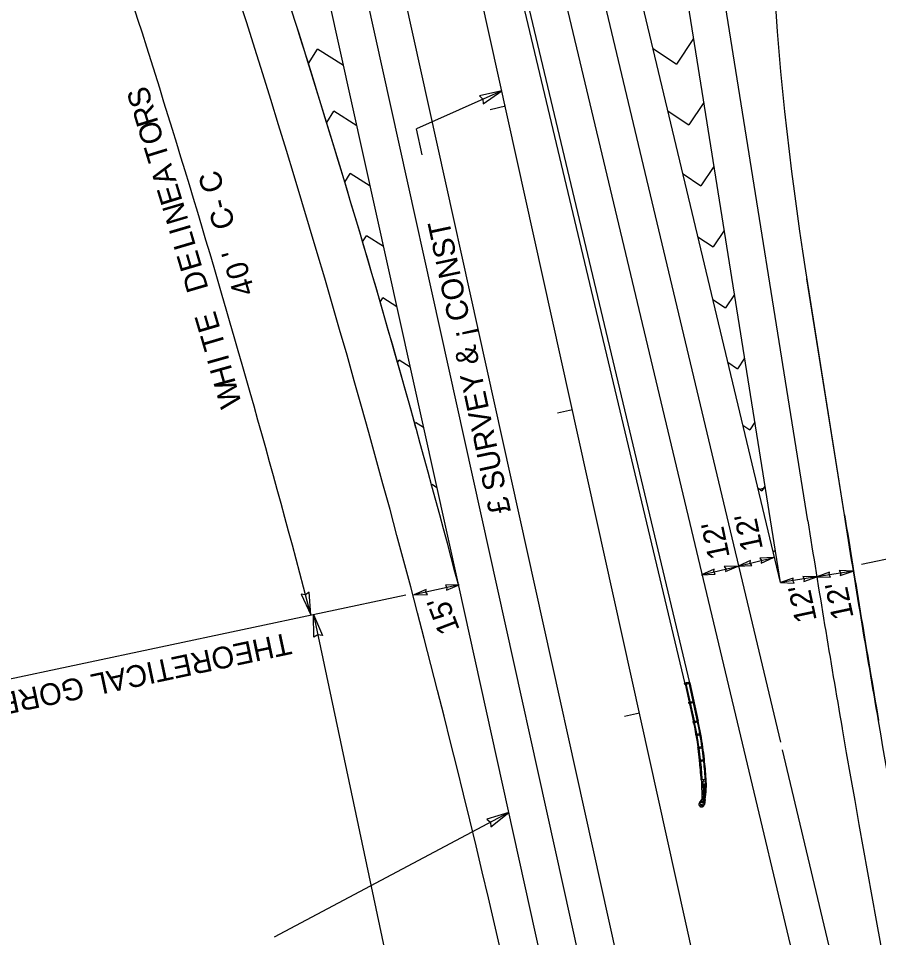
# Model space of a CAD drawing. Extents: x 578088 to 579220, y 1508751 to 1510398.
# Drawn here: x 578418.2 to 578695, y 1509092.1 to 1509387.9 of the extents above; entities that cross this region are included whole.
import ezdxf

# ---------------------------------------------------------------- set-up
doc = ezdxf.new("R2010")
doc.units = 0
for name, color, linetype in [('1', 7, 'Continuous'), ('18', 7, 'Continuous'), ('2', 7, 'Continuous'), ('28', 7, 'Continuous'), ('41', 7, 'Continuous'), ('46', 7, 'Continuous'), ('52', 7, 'Continuous'), ('8', 7, 'Continuous')]:
    doc.layers.add(name, color=color, linetype=linetype)

msp = doc.modelspace()

# ---------------------------------------------------------------- linework, layer by layer
at = {"layer": '1'}
for p, q in [((578639.69, 1509066.69), (578362.17, 1510321.74)), ((578559.88, 1509205.29), (578315.3, 1510311.37))]:
    msp.add_line(p, q, dxfattribs=at)
at = {"layer": '18'}
for p, q in [((578659.48, 1508810.53), (578375.62, 1510094.27)), ((578663.47, 1509155.01), (578558.43, 1509596.29)), ((578672.16, 1509226.28), (578643.76, 1509404.4)), ((578663.36, 1509206.35), (578632.08, 1509402.54)), ((578663.36, 1509206.35), (578617.48, 1509399.06)), ((578635.45, 1509381.4), (578629.99, 1509373.22)), ((578511.53, 1509373.44), (578514.44, 1509378.03)), ((578522.86, 1509372.7), (578514.44, 1509378.03)), ((578622.43, 1509378.26), (578629.99, 1509373.22)), ((578638.73, 1509360.83), (578633.91, 1509353.61)), ((578517.42, 1509354.4), (578519.7, 1509358.01)), ((578527.15, 1509353.3), (578519.7, 1509358.01)), ((578627.24, 1509358.06), (578633.91, 1509353.61)), ((578523.24, 1509335.26), (578524.97, 1509337.99)), ((578531.44, 1509333.9), (578524.97, 1509337.99)), ((578632.05, 1509337.86), (578637.83, 1509334)), ((578642.01, 1509340.26), (578637.83, 1509334)), ((578528.99, 1509315.99), (578530.24, 1509317.97)), ((578535.73, 1509314.49), (578530.24, 1509317.97)), ((578636.86, 1509317.65), (578641.76, 1509314.39)), ((578645.29, 1509319.68), (578641.76, 1509314.39)), ((578684.01, 1509228.17), (578671.91, 1509304.08)), ((578534.66, 1509296.61), (578535.5, 1509297.95)), ((578540.03, 1509295.09), (578535.5, 1509297.95)), ((578641.67, 1509297.45), (578645.68, 1509294.78)), ((578648.57, 1509299.11), (578645.68, 1509294.78)), ((578540.25, 1509277.1), (578540.77, 1509277.93)), ((578544.32, 1509275.69), (578540.77, 1509277.93)), ((578646.48, 1509277.24), (578649.6, 1509275.17)), ((578651.85, 1509278.54), (578649.6, 1509275.17)), ((578655.13, 1509257.96), (578653.52, 1509255.55)), ((578545.76, 1509257.47), (578546.04, 1509257.91)), ((578548.61, 1509256.29), (578546.04, 1509257.91)), ((578651.29, 1509257.04), (578653.52, 1509255.55)), ((578551.2, 1509237.72), (578551.31, 1509237.89)), ((578552.9, 1509236.88), (578551.31, 1509237.89)), ((578658.41, 1509237.39), (578657.44, 1509235.94)), ((578656.1, 1509236.83), (578657.44, 1509235.94)), ((578660.91, 1509216.63), (578661.36, 1509216.33)), ((578661.69, 1509216.82), (578661.36, 1509216.33)), ((578688.9, 1509048.17), (578664.05, 1509152.58))]:
    msp.add_line(p, q, dxfattribs=at)
for centre, radius, start, end in [((579629.37, 1509459.39), 969.97, 176.83826, 189.05927), ((584342.13, 1510130.3), 5741.58, 189.05897, 189.735667), ((584342.13, 1510130.3), 5729.75, 189.05897, 189.730018), ((584342.13, 1510130.3), 5729.75, 189.730019, 192.46846), ((584342.13, 1510130.3), 5741.58, 189.73613, 192.235242)]:
    msp.add_arc(centre, radius, start, end, dxfattribs=at)
at = {"layer": '2'}
for p, q in [((578651.7, 1509152.41), (578547.48, 1509590.23)), ((578656.38, 1509236.37), (578658.33, 1509236.84)), ((578677.17, 1509045.38), (578651.7, 1509152.41))]:
    msp.add_line(p, q, dxfattribs=at)
at = {"layer": '28'}
for p, q in [((578574.92, 1509359.61), (578570.04, 1509358.53)), ((578596.51, 1509261.97), (578591.63, 1509260.89)), ((578618.1, 1509164.33), (578613.22, 1509163.25))]:
    msp.add_line(p, q, dxfattribs=at)
at = {"layer": '41'}
for p, q in [((578671.2, 1508813.02), (578338.64, 1510317)), ((578684.01, 1509228.17), (578671.5, 1509306.66)), ((578684.01, 1509228.17), (578671.5, 1509306.66)), ((578614.13, 1508959.96), (578559.88, 1509205.29))]:
    msp.add_line(p, q, dxfattribs=at)
for centre, radius, start, end in [((574851.28, 1508229.92), 3819.72, 12.46859, 20.71859), ((579629.37, 1509459.39), 969.97, 176.83826, 189.05927), ((579629.37, 1509459.39), 969.97, 176.83826, 189.05927), ((574851.28, 1508229.92), 3834.72, 14.7352, 19.27173), ((584342.13, 1510130.3), 5729.58, 189.05897, 189.729939), ((584342.13, 1510130.3), 5729.58, 189.05897, 189.729939), ((584342.13, 1510130.3), 5729.58, 189.05897, 189.729939)]:
    msp.add_arc(centre, radius, start, end, dxfattribs=at)
at = {"layer": '46'}
for p, q in [((578632.73, 1509173.81), (578580.62, 1509392.73)), ((578634.19, 1509174.14), (578582.08, 1509393.05)), ((578632.56, 1509174.04), (578633.21, 1509174.19)), ((578632.68, 1509173.55), (578632.56, 1509174.04)), ((578633.33, 1509173.7), (578632.68, 1509173.55)), ((578632.73, 1509173.81), (578635.46, 1509161.41)), ((578632.97, 1509173.88), (578635.7, 1509161.47)), ((578633.21, 1509174.19), (578633.86, 1509174.34)), ((578633.21, 1509174.19), (578633.33, 1509173.7)), ((578633.97, 1509173.86), (578633.33, 1509173.7)), ((578633.86, 1509174.34), (578633.97, 1509173.86)), ((578633.92, 1509174.1), (578636.65, 1509161.7)), ((578634.19, 1509174.16), (578636.92, 1509161.76)), ((578633.95, 1509167.86), (578634.6, 1509168.01)), ((578634.06, 1509167.38), (578633.95, 1509167.86)), ((578634.71, 1509167.52), (578634.06, 1509167.38)), ((578634.6, 1509168.01), (578635.25, 1509168.15)), ((578634.6, 1509168.01), (578634.71, 1509167.52)), ((578635.36, 1509167.66), (578634.71, 1509167.52)), ((578635.25, 1509168.15), (578635.36, 1509167.66)), ((578635.29, 1509161.65), (578635.94, 1509161.79)), ((578635.4, 1509161.16), (578635.29, 1509161.65)), ((578636.05, 1509161.31), (578635.4, 1509161.16)), ((578635.94, 1509161.79), (578636.59, 1509161.94)), ((578635.94, 1509161.79), (578636.05, 1509161.31)), ((578636.7, 1509161.45), (578636.05, 1509161.31)), ((578636.59, 1509161.94), (578636.7, 1509161.45)), ((578636.16, 1509157.56), (578636.81, 1509157.68)), ((578636.25, 1509157.07), (578636.16, 1509157.56)), ((578636.81, 1509157.68), (578637.47, 1509157.8)), ((578636.81, 1509157.68), (578636.9, 1509157.19)), ((578637.47, 1509157.8), (578637.56, 1509157.3)), ((578636.9, 1509157.19), (578636.25, 1509157.07)), ((578637.56, 1509157.3), (578636.9, 1509157.19)), ((578636.82, 1509153.43), (578637.48, 1509153.52)), ((578636.88, 1509152.94), (578636.82, 1509153.43)), ((578637.54, 1509153.02), (578636.88, 1509152.94)), ((578637.48, 1509153.52), (578638.14, 1509153.6)), ((578637.48, 1509153.52), (578637.54, 1509153.02)), ((578638.2, 1509153.11), (578637.54, 1509153.02)), ((578638.14, 1509153.6), (578638.2, 1509153.11)), ((578637.3, 1509149.23), (578637.96, 1509149.3)), ((578637.3, 1509149.23), (578637.41, 1509149.24)), ((578637.3, 1509149.22), (578637.3, 1509149.23)), ((578637.35, 1509148.74), (578637.3, 1509149.23)), ((578638.01, 1509148.8), (578637.35, 1509148.74)), ((578637.96, 1509149.3), (578638.62, 1509149.37)), ((578637.96, 1509149.3), (578638.01, 1509148.8)), ((578638.67, 1509148.87), (578638.01, 1509148.8)), ((578638.62, 1509149.37), (578638.67, 1509148.87)), ((578637.91, 1509142.84), (578637.95, 1509142.42)), ((578637.91, 1509142.84), (578637.93, 1509142.84)), ((578639.21, 1509142.96), (578637.93, 1509142.86)), ((578637.93, 1509142.86), (578637.97, 1509142.42)), ((578638.56, 1509142.91), (578638.6, 1509142.44)), ((578638.56, 1509142.89), (578638.58, 1509142.9)), ((578639.25, 1509142.49), (578637.99, 1509142.39)), ((578637.99, 1509142.38), (578638.62, 1509142.43)), ((578638.22, 1509136.93), (578638.05, 1509142.38)), ((578638.98, 1509140.06), (578638.53, 1509137.28)), ((578638.66, 1509138.08), (578638.55, 1509142.43)), ((578639.05, 1509140.06), (578638.61, 1509137.37)), ((578638.62, 1509142.43), (578638.62, 1509142.44)), ((578638.87, 1509141.42), (578638.88, 1509140.06)), ((578639.42, 1509141.42), (578638.87, 1509141.42)), ((578639.43, 1509140.07), (578638.88, 1509140.06)), ((578638.9, 1509141.41), (578638.9, 1509141.45)), ((578638.9, 1509141.45), (578639.15, 1509141.45)), ((578638.93, 1509141.45), (578638.93, 1509141.45)), ((578638.93, 1509141.45), (578639.13, 1509141.45)), ((578638.94, 1509141.53), (578638.94, 1509141.45)), ((578638.97, 1509141.54), (578639.08, 1509141.54)), ((578638.98, 1509141.56), (578638.99, 1509141.57)), ((578638.98, 1509141.56), (578638.98, 1509141.54)), ((578638.99, 1509141.57), (578639.06, 1509141.57)), ((578638.99, 1509141.53), (578638.99, 1509141.45)), ((578639.06, 1509141.57), (578639.07, 1509141.56)), ((578639.06, 1509141.53), (578639.06, 1509141.45)), ((578639.07, 1509141.56), (578639.07, 1509141.54)), ((578639.11, 1509141.53), (578639.11, 1509141.45)), ((578639.13, 1509141.45), (578639.13, 1509141.45)), ((578639.15, 1509141.45), (578639.15, 1509141.42)), ((578639.42, 1509141.41), (578639.43, 1509140.06)), ((578638.23, 1509136.93), (578637.33, 1509135.63)), ((578638.23, 1509136.93), (578637.34, 1509135.62)), ((578637.91, 1509135.99), (578639.02, 1509137.74)), ((578638.21, 1509136.73), (578638.22, 1509136.74)), ((578638.42, 1509136.8), (578638.23, 1509136.93)), ((578638.29, 1509136.7), (578638.27, 1509136.68)), ((578638.4, 1509136.47), (578638.43, 1509136.71)), ((578638.43, 1509136.71), (578638.52, 1509136.69)), ((578638.46, 1509136.87), (578638.44, 1509136.71)), ((578638.48, 1509136.46), (578638.52, 1509136.69)), ((578638.56, 1509137.01), (578638.51, 1509136.69)), ((578638.66, 1509137.42), (578638.65, 1509137.62)), ((578638.66, 1509137.41), (578638.66, 1509137.43)), ((578638.7, 1509137.45), (578638.68, 1509137.77)), ((578638.76, 1509136.35), (578638.71, 1509137.25)), ((578639.14, 1509136.58), (578638.92, 1509136.88)), ((578638.92, 1509136.88), (578638.92, 1509136.87)), ((578639.13, 1509136.57), (578638.92, 1509136.87)), ((578638.93, 1509137.86), (578638.94, 1509137.87)), ((578638.93, 1509137.86), (578638.93, 1509137.84)), ((578638.93, 1509137.84), (578638.94, 1509137.83)), ((578638.97, 1509137.87), (578638.94, 1509137.87)), ((578638.94, 1509137.83), (578638.96, 1509137.83)), ((578638.97, 1509137.88), (578638.96, 1509137.81)), ((578638.97, 1509137.82), (578639.02, 1509137.82)), ((578638.97, 1509137.79), (578639.01, 1509137.79)), ((578639.03, 1509137.89), (578638.98, 1509137.9)), ((578638.98, 1509137.87), (578639.02, 1509137.86)), ((578639.03, 1509137.94), (578639.01, 1509137.75)), ((578639.03, 1509137.94), (578639.04, 1509137.94)), ((578637.16, 1509134.96), (578637.2, 1509134.86)), ((578637.19, 1509134.82), (578637.19, 1509134.82)), ((578637.19, 1509134.82), (578637.19, 1509134.82)), ((578637.27, 1509134.65), (578637.26, 1509134.65)), ((578637.3, 1509134.89), (578637.29, 1509134.87)), ((578637.34, 1509134.53), (578637.3, 1509134.64)), ((578637.89, 1509135.95), (578637.33, 1509135.63)), ((578637.35, 1509135.64), (578637.89, 1509135.95)), ((578637.36, 1509134.85), (578637.35, 1509134.83)), ((578637.5, 1509134.37), (578637.61, 1509134.34)), ((578637.55, 1509135.26), (578637.54, 1509135.24)), ((578637.61, 1509135.21), (578637.6, 1509135.2)), ((578637.62, 1509134.3), (578637.62, 1509134.31)), ((578637.8, 1509135.62), (578637.79, 1509135.6)), ((578637.79, 1509134.23), (578637.8, 1509134.24)), ((578637.8, 1509136.14), (578637.94, 1509136.36)), ((578637.93, 1509134.21), (578637.83, 1509134.25)), ((578637.86, 1509135.58), (578637.85, 1509135.56)), ((578638, 1509136.31), (578637.86, 1509136.1)), ((578638.19, 1509136.43), (578637.99, 1509136.57)), ((578638.45, 1509135.5), (578638, 1509135.67)), ((578638.1, 1509135.98), (578638.17, 1509136.39)), ((578638.13, 1509135.97), (578638.1, 1509135.98)), ((578638.11, 1509135.89), (578638.19, 1509136.42)), ((578638.74, 1509135.79), (578638.11, 1509135.89)), ((578638.75, 1509135.86), (578638.12, 1509135.96)), ((578638.16, 1509134.21), (578638.26, 1509134.26)), ((578638.16, 1509134.21), (578638.26, 1509134.26)), ((578638.19, 1509136.44), (578638.34, 1509136.41)), ((578638.19, 1509136.42), (578638.82, 1509136.33)), ((578638.25, 1509136.43), (578638.24, 1509136.52)), ((578638.25, 1509135.79), (578638.26, 1509135.86)), ((578638.27, 1509135.78), (578638.4, 1509135.76)), ((578638.29, 1509135.79), (578638.3, 1509135.86)), ((578638.29, 1509135.78), (578638.29, 1509135.74)), ((578638.29, 1509135.74), (578638.29, 1509135.73)), ((578638.29, 1509135.73), (578638.36, 1509135.72)), ((578638.29, 1509134.25), (578638.3, 1509134.24)), ((578638.3, 1509134.24), (578638.29, 1509134.25)), ((578638.35, 1509136.47), (578638.34, 1509136.4)), ((578638.36, 1509134.46), (578638.35, 1509134.44)), ((578638.37, 1509135.72), (578638.36, 1509135.72)), ((578638.37, 1509136.48), (578638.5, 1509136.46)), ((578638.38, 1509135.76), (578638.37, 1509135.72)), ((578638.39, 1509136.46), (578638.38, 1509136.39)), ((578638.38, 1509135.78), (578638.39, 1509135.84)), ((578638.42, 1509135.77), (578638.43, 1509135.84)), ((578638.42, 1509134.9), (578638.42, 1509134.88)), ((578638.43, 1509134.45), (578638.43, 1509134.43)), ((578638.48, 1509136.45), (578638.47, 1509136.38)), ((578638.47, 1509134.32), (578638.47, 1509134.32)), ((578638.49, 1509135.33), (578638.48, 1509135.31)), ((578638.58, 1509134.39), (578638.48, 1509134.36)), ((578638.5, 1509134.88), (578638.49, 1509134.86)), ((578638.52, 1509136.44), (578638.51, 1509136.37)), ((578638.51, 1509136.39), (578638.82, 1509136.34)), ((578638.56, 1509135.32), (578638.56, 1509135.3)), ((578638.86, 1509136.61), (578638.72, 1509135.64)), ((578638.72, 1509135.64), (578638.9, 1509135.03)), ((578638.82, 1509136.33), (578638.75, 1509135.86)), ((578638.89, 1509135.97), (578638.85, 1509135.71)), ((578638.86, 1509136.61), (578639.13, 1509136.57)), ((578639.13, 1509136.57), (578638.9, 1509135.01)), ((578639.14, 1509136.58), (578638.91, 1509135.01)), ((578638.92, 1509135.7), (578638.96, 1509135.96)), ((578638.94, 1509136.44), (578638.94, 1509136.42)), ((578639.01, 1509136.41), (578639.02, 1509136.43))]:
    msp.add_line(p, q, dxfattribs=at)
msp.add_circle((578637.92, 1509134.81), 0.25, dxfattribs=at)
for centre, radius, start, end in [((578637.99, 1509142.42), 0.0423, 184.766, 274.766), ((578637.99, 1509142.42), 0.0267, 184.766, 274.766), ((578638.29, 1509142.4), 0.0417, 184.766, 4.766), ((578638.97, 1509141.5), 0.0374, 49.0302, 131.4244), ((578639.03, 1509141.47), 0.0674, 59.8574, 120.5972), ((578639.08, 1509141.5), 0.0374, 49.0302, 131.4244), ((578638.24, 1509136.7), 0.0383, 145.5759, 325.5759), ((578638.25, 1509136.72), 0.0383, 325.5759, 145.5759), ((578639, 1509137.84), 0.0335, 128.4484, 219.1028), ((578638.98, 1509137.8), 0.0159, 105.7077, 241.8435), ((578638.98, 1509137.88), 0.0159, 105.7077, 241.8435), ((578638.03, 1509135.08), 0.887, 141.8882, 355.264), ((578638.03, 1509135.09), 0.887, 160.5258, 188.5762), ((578638.03, 1509135.08), 0.877, 141.8882, 355.264), ((578638.03, 1509135.09), 0.887, 197.5339, 209.6185), ((578637.18, 1509134.85), 0.0267, 293.5761, 27.0398), ((578637.27, 1509134.63), 0.0267, 20.1128, 113.5762), ((578637.32, 1509134.85), 0.0383, 145.5762, 325.5762), ((578637.33, 1509134.87), 0.0383, 325.5762, 145.5762), ((578638.03, 1509135.09), 0.887, 218.5762, 233.5762), ((578637.57, 1509135.22), 0.0383, 145.5762, 325.5762), ((578637.58, 1509135.23), 0.0383, 325.5762, 145.5762), ((578637.6, 1509134.31), 0.0267, 338.5762, 72.0399), ((578638.03, 1509135.09), 0.887, 242.5338, 254.6185), ((578637.82, 1509135.58), 0.0383, 145.5762, 325.5762), ((578637.82, 1509136.12), 0.0367, 145.5762, 325.5762), ((578637.83, 1509135.6), 0.0383, 325.5762, 145.5762), ((578637.82, 1509134.23), 0.0267, 65.1124, 158.5762), ((578638.08, 1509135.86), 0.21, 145.5762, 248.5762), ((578638.03, 1509135.09), 0.887, 263.5762, 278.5762), ((578637.97, 1509136.33), 0.0367, 325.5762, 145.5762), ((578638.27, 1509135.8), 0.021, 189.319, 333.8333), ((578638.27, 1509134.23), 0.0267, 23.5762, 117.0396), ((578638.27, 1509134.23), 0.0267, 23.5762, 117.0399), ((578638.34, 1509135.84), 0.0719, 224.4419, 298.7105), ((578638.03, 1509135.09), 0.887, 287.5339, 299.6185), ((578638.37, 1509136.45), 0.021, 9.319, 153.8333), ((578638.39, 1509134.43), 0.0383, 171.5762, 351.5762), ((578638.39, 1509134.45), 0.0383, 351.5762, 171.5762), ((578638.4, 1509135.78), 0.021, 189.319, 333.8333), ((578638.43, 1509136.39), 0.0719, 44.4419, 118.7105), ((578638.46, 1509134.89), 0.0383, 351.5762, 171.5762), ((578638.46, 1509134.87), 0.0383, 171.5762, 351.5762), ((578638.52, 1509135.69), 0.21, 248.5762, 341.677), ((578638.49, 1509134.33), 0.0267, 110.1128, 203.5762), ((578638.5, 1509136.44), 0.021, 9.319, 153.8333), ((578638.52, 1509135.31), 0.0383, 171.5762, 351.5762), ((578638.52, 1509135.33), 0.0383, 351.5762, 171.5762), ((578638.5, 1509136.39), 0.0417, 351.5761, 64.9368), ((578638.03, 1509135.09), 0.887, 308.5762, 336.6266), ((578638.88, 1509135.7), 0.0367, 171.5762, 351.5762), ((578638.92, 1509135.96), 0.0367, 351.5762, 171.5762), ((578638.98, 1509136.44), 0.0383, 351.5764, 171.5764), ((578638.97, 1509136.42), 0.0383, 171.5764, 351.5764)]:
    msp.add_arc(centre, radius, start, end, dxfattribs=at)
for centre, major_axis, ratio, start_param, end_param in [((578550.81, 1509141.99), (20.86, -87.61), 0.964286, 1.468642, 1.562826), ((578550.78, 1509141.99), (20.93, -87.88), 0.964395, 1.468642, 1.562826), ((578552, 1509142.28), (20.86, -87.61), 0.964286, 1.468642, 1.562826), ((578552, 1509142.28), (20.93, -87.88), 0.964395, 1.468642, 1.562826), ((578510.2, 1509136.87), (31.16, -130.86), 0.948697, 1.440864, 1.468634), ((578513.48, 1509137.5), (30.61, -128.57), 0.943102, 1.439674, 1.468634), ((578511.49, 1509137.29), (31.16, -130.86), 0.948697, 1.439884, 1.468634), ((578514.7, 1509137.78), (30.61, -128.57), 0.943102, 1.439551, 1.468634), ((578510.2, 1509136.87), (31.16, -130.86), 0.948697, 1.393285, 1.440864), ((578513.48, 1509137.5), (30.61, -128.57), 0.943102, 1.39137, 1.439674), ((578511.49, 1509137.29), (31.16, -130.86), 0.948697, 1.393285, 1.439884), ((578514.7, 1509137.78), (30.61, -128.57), 0.943102, 1.39137, 1.439551), ((578610.86, 1509140.41), (27.73, 6.6), 0.937456, 5.89231, 6.141691), ((578611.14, 1509140.37), (27.73, 6.6), 0.937456, 5.89231, 6.141691), ((578642.22, 1509132.05), (0.8, 7.04), 0.813532, 0.727223, 0.900583), ((578642.22, 1509132.05), (0.8, 7.03), 0.813845, 0.726535, 0.900584)]:
    msp.add_ellipse(centre, major_axis=major_axis, ratio=ratio, start_param=start_param, end_param=end_param, dxfattribs=at)
at = {"layer": '52'}
for p, q in [((578573.81, 1509364.63), (578546.33, 1509352.32)), ((578573.81, 1509364.63), (578566.62, 1509362.94)), ((578567.74, 1509360.44), (578573.81, 1509364.63)), ((578566.62, 1509362.94), (578567.69, 1509361.89)), ((578567.69, 1509361.89), (578567.74, 1509360.44)), ((578548.09, 1509344.04), (578546.33, 1509352.32)), ((578869.57, 1509250.44), (578689.51, 1509212.17)), ((578649.74, 1509211.7), (578661.2, 1509214.42)), ((578661.2, 1509214.42), (578656.78, 1509214.23)), ((578656.78, 1509214.23), (578657.29, 1509213.49)), ((578657.16, 1509212.63), (578661.2, 1509214.42)), ((578638.02, 1509208.9), (578649.74, 1509211.7)), ((578642.06, 1509210.7), (578638.02, 1509208.91)), ((578641.93, 1509209.84), (578642.06, 1509210.7)), ((578649.74, 1509211.7), (578645.32, 1509211.51)), ((578645.32, 1509211.51), (578645.83, 1509210.77)), ((578645.7, 1509209.9), (578649.74, 1509211.7)), ((578645.83, 1509210.77), (578645.7, 1509209.9)), ((578653.79, 1509213.49), (578649.74, 1509211.7)), ((578649.74, 1509211.7), (578654.17, 1509211.89)), ((578653.66, 1509212.63), (578653.79, 1509213.49)), ((578654.17, 1509211.89), (578653.66, 1509212.63)), ((578657.29, 1509213.49), (578657.16, 1509212.63)), ((578638.02, 1509208.91), (578642.44, 1509209.09)), ((578642.44, 1509209.09), (578641.93, 1509209.84)), ((578675.04, 1509208.22), (578663.36, 1509206.35)), ((578667.52, 1509207.84), (578663.36, 1509206.35)), ((578667.33, 1509206.99), (578667.52, 1509207.84)), ((578675.04, 1509208.22), (578670.61, 1509208.36)), ((578670.61, 1509208.36), (578671.07, 1509207.58)), ((578670.87, 1509206.73), (578675.04, 1509208.22)), ((578686.73, 1509210.08), (578675.04, 1509208.22)), ((578679.21, 1509209.7), (578675.04, 1509208.22)), ((578675.04, 1509208.22), (578679.47, 1509208.07)), ((578679.01, 1509208.85), (578679.21, 1509209.7)), ((578679.47, 1509208.07), (578679.01, 1509208.85)), ((578686.73, 1509210.08), (578682.3, 1509210.23)), ((578682.3, 1509210.23), (578682.76, 1509209.45)), ((578682.56, 1509208.6), (578686.73, 1509210.08)), ((578682.76, 1509209.45), (578682.56, 1509208.6)), ((578560.04, 1509205.69), (578545.41, 1509202.41)), ((578560.04, 1509205.69), (578555.61, 1509205.56)), ((578555.61, 1509205.56), (578556.12, 1509204.81)), ((578555.97, 1509203.95), (578560.04, 1509205.69)), ((578556.12, 1509204.81), (578555.97, 1509203.95)), ((578663.36, 1509206.35), (578667.78, 1509206.21)), ((578667.78, 1509206.21), (578667.33, 1509206.99)), ((578671.07, 1509207.58), (578670.87, 1509206.73)), ((578405.02, 1509173.15), (578542.9, 1509202.46)), ((578510.62, 1509202.44), (578509.18, 1509202.63)), ((578509.18, 1509202.63), (578512.32, 1509195.96)), ((578511.84, 1509203.32), (578510.62, 1509202.44)), ((578512.32, 1509195.96), (578511.84, 1509203.32)), ((578549.47, 1509204.15), (578545.41, 1509202.41)), ((578545.41, 1509202.41), (578549.83, 1509202.54)), ((578549.33, 1509203.29), (578549.47, 1509204.15)), ((578549.83, 1509202.54), (578549.33, 1509203.29)), ((578513.15, 1509196.13), (578592.43, 1508823.18)), ((578513.15, 1509196.13), (578516.03, 1509189.33)), ((578513.34, 1509188.76), (578513.15, 1509196.13)), ((578514.55, 1509189.58), (578513.34, 1509188.76)), ((578516.03, 1509189.33), (578514.55, 1509189.58)), ((578575.99, 1509132.43), (578500.53, 1509092.24)), ((578575.99, 1509132.43), (578568.94, 1509130.26)), ((578570.23, 1509127.83), (578575.99, 1509132.43)), ((578568.94, 1509130.26), (578570.08, 1509129.28)), ((578570.08, 1509129.28), (578570.23, 1509127.83))]:
    msp.add_line(p, q, dxfattribs=at)
msp.add_arc((574817.44, 1508227.41), 3819.72, 14.68854, 19.14283, dxfattribs=at)
at = {"layer": '8'}
msp.add_arc((574851.28, 1508229.92), 3834.72, 15.5225, 18.32289, dxfattribs=at)

# ---------------------------------------------------------------- texts
at = {"layer": '52'}
for s, rotation, p in [('S', 107.1167, (578461.48, 1509360.57)), ('R', 107.1167, (578463.38, 1509354.4)), ('O', 107.1167, (578465.16, 1509348.61)), ('T', 107.1167, (578466.9, 1509342.95)), ('A', 107.1167, (578469.17, 1509335.6)), ('C', 107.1167, (578484.6, 1509333.06)), ('E', 107.1167, (578471.14, 1509329.19)), ('-', 103.5467, (578486.13, 1509327.38)), ('N', 106.4229, (578473, 1509322.93)), ('C', 106.4229, (578488.1, 1509321.21)), ('I', 106.4229, (578473.94, 1509319.75)), ('£ SURVEY & ¡ CONST', 102, (578576.71, 1509229.26)), ('L', 106.4229, (578475.42, 1509314.71)), ('E', 106.4229, (578477.47, 1509307.77)), ("'", 106.4229, (578490.63, 1509312.61)), ('0', 106.4229, (578492.8, 1509305.27)), ('D', 106.4229, (578479.46, 1509301)), ('4', 106.4229, (578494.42, 1509299.77)), ('E', 106.4229, (578483.26, 1509288.1)), ('T', 106.4229, (578484.98, 1509282.26)), ('I', 105.7292, (578486.22, 1509277.8)), ('H', 105.7292, (578488.25, 1509270.57)), ('W', 105.7292, (578490.19, 1509263.7)), ("12'", 102, (578657.8, 1509217.28)), ("12'", 102, (578647.14, 1509214.66)), ("12'", 102, (578686.97, 1509195.24)), ("12'", 102, (578675.12, 1509194.29)), ("15'", 110.8713, (578560.32, 1509191.24)), ('THEORETICAL GORE', 192, (578505.14, 1509190.33))]:
    msp.add_text(s, height=7, rotation=rotation, dxfattribs=at).set_placement(p)

doc.saveas('drawing.dxf')
